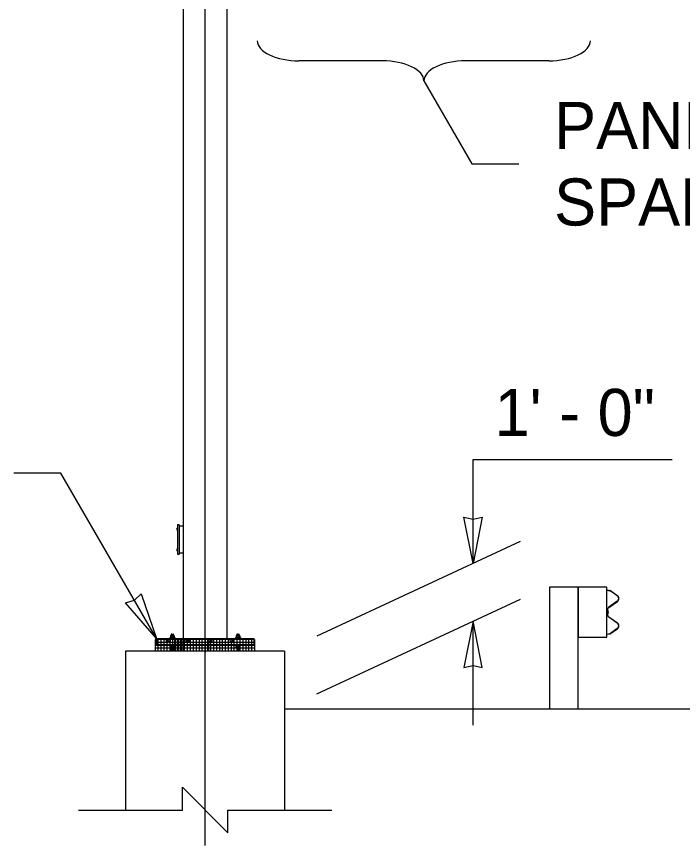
# Model space of a CAD drawing. Extents: x 99862 to 104211, y 98939 to 111076.
# Drawn here: x 100719.8 to 100945.9, y 100893.9 to 101175.5 of the extents above; entities that cross this region are included whole.
import ezdxf

# ---------------------------------------------------------------- set-up
doc = ezdxf.new("R2010")
doc.units = 0
for name, color, linetype in [('Level 15', 7, 'Continuous'), ('Level 20', 7, 'Continuous'), ('Level 22', 7, 'Continuous'), ('Level 3', 7, 'Continuous'), ('Level 36', 7, 'Continuous'), ('Level 4', 7, 'Continuous'), ('Level 6', 7, 'Continuous'), ('Level 62', 7, 'Continuous'), ('Level 7', 7, 'Continuous'), ('Level 9', 7, 'Continuous')]:
    doc.layers.add(name, color=color, linetype=linetype)

msp = doc.modelspace()

# ---------------------------------------------------------------- linework, layer by layer
at = {"layer": 'Level 15'}
for p, q in [((100783.8, 100893.86), (100783.8, 101626.74)), ((100843.96, 101160.49), (100815.67, 101160.49)), ((100900.53, 101160.49), (100872.25, 101160.49)), ((100858.1, 101153.67), (100874.35, 101125.52)), ((100874.35, 101125.52), (100890.35, 101125.52)), ((100874.8, 100989.71), (100874.8, 101025.02)), ((100874.8, 101025.02), (100942.43, 101025.02)), ((100734.8, 101020.38), (100718.8, 101020.38)), ((100767.3, 100964.24), (100734.8, 101020.38)), ((100890.8, 100997.17), (100821.75, 100964.97)), ((100890.8, 100977.48), (100821.64, 100945.23)), ((100874.8, 100934.71), (100874.8, 100970.02))]:
    msp.add_line(p, q, dxfattribs=at)
for points in [[(100874.8, 100989.71), (100871.72, 101005.43), (100874.8, 101004.71), (100877.89, 101005.43)], [(100767.3, 100964.24), (100756.77, 100976.32), (100759.81, 100977.23), (100762.11, 100979.4)], [(100874.8, 100970.02), (100871.72, 100954.3), (100874.8, 100955.02), (100877.89, 100954.3)]]:
    msp.add_lwpolyline(points, close=True, dxfattribs=at)
msp.add_lwpolyline([(100740.8, 100905.86), (100776.06, 100905.86), (100776.06, 100913.61), (100791.55, 100898.12), (100791.55, 100905.86), (100826.8, 100905.86)], dxfattribs=at)
for centre, major_axis, start_param, end_param in [((100815.67, 101167.3), (-14.14, 0), 6.283174, 7.853982), ((100900.53, 101167.3), (14.14, 0), 4.712389, 6.283196), ((100843.96, 101153.67), (14.14, 0), 6.283174, 7.853982), ((100872.25, 101153.67), (-14.14, 0), 4.712389, 6.283196)]:
    msp.add_ellipse(centre, major_axis=major_axis, ratio=0.481891, start_param=start_param, end_param=end_param, dxfattribs=at)
at = {"layer": 'Level 22'}
for p, q in [((100766.8, 100963.88), (100766.8, 100959.86)), ((100769.22, 100963.84), (100766.8, 100963.84)), ((100770.93, 100962.85), (100766.8, 100962.85)), ((100800.58, 100961.86), (100766.8, 100961.86)), ((100767.79, 100963.88), (100767.79, 100963.02)), ((100767.79, 100963.02), (100767.79, 100959.86)), ((100768.79, 100963.88), (100768.79, 100963.02)), ((100768.79, 100963.02), (100768.79, 100959.87)), ((100770.86, 100963.84), (100769.22, 100963.84)), ((100769.78, 100963.88), (100769.78, 100959.86)), ((100770.77, 100963.88), (100770.77, 100963.74)), ((100770.77, 100963.01), (100770.77, 100959.86)), ((100774.51, 100962.85), (100771.65, 100962.85)), ((100774.51, 100963.84), (100771.72, 100963.84)), ((100771.76, 100963.88), (100771.76, 100963.8)), ((100771.76, 100962.95), (100771.76, 100959.86)), ((100772.75, 100963.88), (100772.75, 100959.86)), ((100773.4, 100963.88), (100773.4, 100959.86)), ((100773.75, 100963.88), (100773.75, 100959.86)), ((100774.39, 100963.88), (100774.39, 100959.86)), ((100777.54, 100963.84), (100774.51, 100963.84)), ((100777.63, 100962.85), (100774.51, 100962.85)), ((100774.74, 100963.88), (100774.74, 100959.86)), ((100775.38, 100963.88), (100775.38, 100959.86)), ((100775.73, 100963.88), (100775.73, 100959.86)), ((100776.38, 100963.88), (100776.38, 100959.86)), ((100776.72, 100963.88), (100776.72, 100959.86)), ((100777.46, 100963.88), (100777.46, 100963.73)), ((100777.72, 100962.8), (100777.72, 100959.86)), ((100784.52, 100962.85), (100778.34, 100962.85)), ((100784.57, 100963.84), (100778.42, 100963.84)), ((100778.45, 100963.88), (100778.45, 100963.8)), ((100778.72, 100963.88), (100778.72, 100959.86)), ((100779.72, 100963.88), (100779.72, 100959.86)), ((100780.72, 100963.88), (100780.72, 100959.86)), ((100781.72, 100963.88), (100781.72, 100959.86)), ((100782.69, 100963.88), (100782.69, 100959.86)), ((100783.67, 100963.88), (100783.67, 100959.86)), ((100785.11, 100962.85), (100784.5, 100962.85)), ((100785.04, 100963.84), (100784.57, 100963.84)), ((100784.66, 100963.89), (100784.66, 100959.86)), ((100785.65, 100962.76), (100785.65, 100959.86)), ((100792.58, 100962.85), (100785.83, 100962.85)), ((100787.01, 100963.84), (100785.9, 100963.84)), ((100786.65, 100963.88), (100786.65, 100962.95)), ((100786.65, 100962.95), (100786.65, 100959.86)), ((100790.52, 100963.84), (100787.01, 100963.84)), ((100787.64, 100963.88), (100787.64, 100959.86)), ((100788.63, 100963.88), (100788.63, 100959.86)), ((100789.62, 100963.88), (100789.62, 100959.86)), ((100792.53, 100963.84), (100790.52, 100963.84)), ((100790.61, 100963.88), (100790.61, 100959.86)), ((100791.61, 100963.88), (100791.61, 100959.86)), ((100792.49, 100963.88), (100792.49, 100963.8)), ((100792.6, 100962.85), (100792.6, 100959.86)), ((100792.6, 100962.85), (100792.6, 100962.85)), ((100800.58, 100962.85), (100793.32, 100962.85)), ((100800.58, 100963.84), (100793.39, 100963.84)), ((100793.59, 100963.88), (100793.59, 100959.86)), ((100794.58, 100963.88), (100794.58, 100959.86)), ((100795.58, 100963.88), (100795.58, 100959.86)), ((100796.58, 100963.88), (100796.58, 100959.86)), ((100797.58, 100963.88), (100797.58, 100959.86)), ((100798.58, 100963.88), (100798.58, 100959.86)), ((100799.58, 100963.88), (100799.58, 100959.86)), ((100800.58, 100963.84), (100800.58, 100959.86)), ((100800.58, 100960.87), (100766.8, 100960.87))]:
    msp.add_line(p, q, dxfattribs=at)
for centre in [(100771.29, 100963.37), (100777.98, 100963.37), (100785.47, 100963.37), (100792.96, 100963.37)]:
    msp.add_circle(centre, 0.635, dxfattribs=at)
at = {"layer": 'Level 3'}
for p, q in [((100776.3, 101460.3), (100776.3, 101002.33)), ((100791.3, 101002.33), (100791.3, 101340.4))]:
    msp.add_line(p, q, dxfattribs=at)
at = {"layer": 'Level 36'}
msp.add_line((100920.47, 100973.94), (100920.47, 100972.34), dxfattribs=at)
msp.add_arc((100919.82, 100973.14), 1.03, 309.0733, 50.9267, dxfattribs=at)
at = {"layer": 'Level 4'}
for p, q in [((100776.3, 101002.33), (100776.3, 100964.24)), ((100791.3, 100964.24), (100791.3, 101002.33)), ((100920.32, 100980.68), (100920.3, 100980.6)), ((100920.3, 100980.6), (100921.29, 100980.43)), ((100920.32, 100980.68), (100921.3, 100980.5)), ((100923.79, 100978.72), (100921.47, 100980.35)), ((100921.51, 100980.42), (100923.84, 100978.78)), ((100923.79, 100976.85), (100920.91, 100974.82)), ((100920.95, 100974.76), (100923.84, 100976.79)), ((100920.39, 100973.14), (100920.39, 100973.82)), ((100920.39, 100973.14), (100920.39, 100972.45)), ((100920.47, 100973.14), (100920.47, 100973.82)), ((100920.47, 100973.14), (100920.47, 100972.45)), ((100923.79, 100969.43), (100920.91, 100971.46)), ((100920.95, 100971.52), (100923.84, 100969.49)), ((100923.79, 100967.56), (100921.47, 100965.92)), ((100921.51, 100965.86), (100923.84, 100967.49)), ((100920.3, 100965.67), (100921.29, 100965.84)), ((100920.32, 100965.6), (100920.3, 100965.67)), ((100920.32, 100965.6), (100921.3, 100965.77))]:
    msp.add_line(p, q, dxfattribs=at)
for centre, radius, start, end in [((100921.21, 100979.98), 0.457, 54.8459, 80), ((100921.21, 100979.98), 0.533, 54.852, 80), ((100923.14, 100977.78), 1.14, 305.1469, 54.8387), ((100923.14, 100977.78), 1.22, 305.1461, 54.8378), ((100921.61, 100973.82), 1.22, 125.1621, 180), ((100921.61, 100973.82), 1.14, 125.1612, 179.9897), ((100921.61, 100972.45), 1.22, 180, 234.8379), ((100921.61, 100972.45), 1.14, 180.0103, 234.8388), ((100923.14, 100968.49), 1.14, 305.1613, 54.8531), ((100923.14, 100968.49), 1.22, 305.1622, 54.8539), ((100921.21, 100966.29), 0.457, 280, 305.1541), ((100921.21, 100966.29), 0.533, 280, 305.148)]:
    msp.add_arc(centre, radius, start, end, dxfattribs=at)
at = {"layer": 'Level 6'}
for p, q in [((100776.55, 100964.08), (100776.55, 100963.65)), ((100776.55, 100963.05), (100776.55, 100962.62)), ((100776.55, 100962.03), (100776.55, 100961.59)), ((100776.55, 100960.8), (100776.55, 100960.36))]:
    msp.add_line(p, q, dxfattribs=at)
at = {"layer": 'Level 62'}
for points, degree in [([(100773.04, 100965.54), (100773.05, 100965.53), (100773.01, 100965.52), (100772.93, 100965.52), (100772.69, 100965.51), (100772.38, 100965.49), (100772.3, 100965.48), (100772.3, 100965.48), (100772.29, 100965.48), (100772.29, 100965.47)], 4), ([(100772.48, 100965.62), (100772.39, 100965.61), (100772.33, 100965.61), (100772.3, 100965.6)], 3), ([(100773.04, 100965.16), (100773.05, 100965.16), (100773.03, 100965.15), (100772.99, 100965.15)], 3), ([(100795.32, 100965.54), (100795.32, 100965.53), (100795.28, 100965.52), (100795.2, 100965.52), (100794.97, 100965.51), (100794.66, 100965.49), (100794.58, 100965.48), (100794.57, 100965.48), (100794.57, 100965.48), (100794.57, 100965.47)], 4), ([(100794.76, 100965.62), (100794.66, 100965.61), (100794.6, 100965.61), (100794.58, 100965.6)], 3), ([(100795.32, 100965.16), (100795.32, 100965.16), (100795.3, 100965.15), (100795.26, 100965.15)], 3), ([(100772.97, 100960.28), (100772.98, 100960.27), (100772.96, 100960.27), (100772.93, 100960.27), (100772.78, 100960.25), (100772.51, 100960.24), (100772.38, 100960.23), (100772.36, 100960.23), (100772.34, 100960.23), (100772.34, 100960.22)], 4), ([(100772.97, 100960.07), (100772.98, 100960.06), (100772.96, 100960.06), (100772.93, 100960.05), (100772.78, 100960.04), (100772.51, 100960.03), (100772.38, 100960.02), (100772.36, 100960.02), (100772.34, 100960.02), (100772.34, 100960.01)], 4), ([(100772.99, 100961.05), (100773, 100961.04), (100772.98, 100961.04), (100772.94, 100961.04), (100772.8, 100961.02), (100772.53, 100961.01), (100772.4, 100961), (100772.37, 100961), (100772.36, 100961), (100772.36, 100960.99)], 4), ([(100772.99, 100960.83), (100773, 100960.83), (100772.98, 100960.83), (100772.94, 100960.82), (100772.8, 100960.81), (100772.53, 100960.8), (100772.4, 100960.79), (100772.37, 100960.79), (100772.36, 100960.79), (100772.36, 100960.78)], 4), ([(100772.99, 100960.66), (100773, 100960.66), (100772.98, 100960.65), (100772.94, 100960.65), (100772.8, 100960.64), (100772.53, 100960.63), (100772.4, 100960.61), (100772.37, 100960.61), (100772.36, 100960.61), (100772.36, 100960.61)], 4), ([(100772.99, 100960.45), (100773, 100960.44), (100772.98, 100960.44), (100772.94, 100960.44), (100772.8, 100960.43), (100772.53, 100960.41), (100772.4, 100960.4), (100772.37, 100960.4), (100772.36, 100960.4), (100772.36, 100960.4)], 4), ([(100790.37, 100960.89), (100790.38, 100960.88), (100790.36, 100960.88), (100790.32, 100960.88), (100790.18, 100960.87), (100789.91, 100960.85), (100789.78, 100960.84), (100789.76, 100960.84), (100789.74, 100960.84), (100789.74, 100960.84)], 4), ([(100795.27, 100961.09), (100795.28, 100961.08), (100795.26, 100961.08), (100795.22, 100961.08), (100795.07, 100961.06), (100794.8, 100961.05), (100794.68, 100961.04), (100794.66, 100961.04), (100794.64, 100961.04), (100794.64, 100961.03)], 4), ([(100795.27, 100960.88), (100795.28, 100960.87), (100795.26, 100960.87), (100795.23, 100960.87), (100795.08, 100960.85), (100794.81, 100960.84), (100794.68, 100960.83), (100794.66, 100960.83), (100794.64, 100960.83), (100794.64, 100960.82)], 4), ([(100795.27, 100960.87), (100795.28, 100960.87), (100795.26, 100960.86), (100795.23, 100960.86), (100795.08, 100960.85), (100794.81, 100960.84), (100794.68, 100960.82), (100794.66, 100960.82), (100794.64, 100960.82), (100794.64, 100960.82)], 4), ([(100795.27, 100960.66), (100795.28, 100960.65), (100795.26, 100960.65), (100795.23, 100960.65), (100795.08, 100960.64), (100794.81, 100960.62), (100794.68, 100960.61), (100794.66, 100960.61), (100794.64, 100960.61), (100794.64, 100960.61)], 4), ([(100795.27, 100960.45), (100795.28, 100960.44), (100795.26, 100960.44), (100795.23, 100960.44), (100795.08, 100960.43), (100794.81, 100960.41), (100794.68, 100960.4), (100794.66, 100960.4), (100794.64, 100960.4), (100794.64, 100960.4)], 4), ([(100795.27, 100960.23), (100795.28, 100960.23), (100795.26, 100960.22), (100795.23, 100960.22), (100795.08, 100960.21), (100794.81, 100960.2), (100794.68, 100960.19), (100794.66, 100960.18), (100794.64, 100960.18), (100794.64, 100960.18)], 4), ([(100795.27, 100960.02), (100795.28, 100960.02), (100795.26, 100960.01), (100795.23, 100960.01), (100795.08, 100960), (100794.81, 100959.99), (100794.68, 100959.98), (100794.66, 100959.97), (100794.64, 100959.97), (100794.64, 100959.97)], 4)]:
    msp.add_open_spline(points, degree=degree, dxfattribs=at)
at = {"layer": 'Level 7'}
for p, q in [((100910.55, 100981.67), (100900.8, 100981.67)), ((100900.8, 100981.67), (100900.8, 100940.18)), ((100910.55, 100940.18), (100910.55, 100981.67)), ((100767.3, 100964.24), (100767.3, 100961.99)), ((100767.3, 100964.24), (100800.3, 100964.24)), ((100800.3, 100964.24), (100800.3, 100961.99)), ((100800.3, 100961.99), (100767.3, 100961.99)), ((100810.8, 100959.86), (100756.8, 100959.86)), ((100756.8, 100959.86), (100756.8, 100905.86)), ((100810.8, 100959.86), (100810.8, 100905.86)), ((102186.87, 100940.18), (100810.8, 100940.18))]:
    msp.add_line(p, q, dxfattribs=at)
msp.add_lwpolyline([(100920.3, 100981.67), (100910.55, 100981.67), (100910.55, 100964.61), (100920.3, 100964.61)], close=True, dxfattribs=at)
at = {"layer": 'Level 9'}
for p, q in [((100774.43, 101002.8), (100774.43, 100999.33)), ((100774.99, 101002.8), (100774.43, 101002.8)), ((100774.99, 101002.8), (100774.99, 100999.33)), ((100776.3, 101002.33), (100774.99, 101002.33)), ((100774.43, 100999.33), (100774.43, 100996.33)), ((100774.99, 100999.33), (100774.99, 100996.33)), ((100774.43, 100996.33), (100774.43, 100992.86)), ((100774.99, 100996.33), (100774.99, 100992.86)), ((100774.43, 100992.86), (100774.99, 100992.86)), ((100774.99, 100993.33), (100776.3, 100993.33)), ((100771.83, 100964.49), (100773.5, 100964.49)), ((100771.83, 100964.49), (100771.83, 100964.37)), ((100771.83, 100964.37), (100773.5, 100964.37)), ((100771.83, 100964.37), (100771.83, 100964.24)), ((100771.83, 100964.24), (100773.5, 100964.24)), ((100772.1, 100965.15), (100772.02, 100965.1)), ((100772.02, 100965.1), (100772.02, 100964.49)), ((100772.34, 100964.49), (100772.02, 100964.49)), ((100772.18, 100965.15), (100772.1, 100965.15)), ((100772.18, 100965.15), (100772.18, 100965.15)), ((100772.65, 100965.15), (100772.18, 100965.15)), ((100772.38, 100965.67), (100772.29, 100965.62)), ((100772.29, 100965.62), (100772.29, 100965.15)), ((100772.34, 100965.1), (100772.34, 100964.49)), ((100772.99, 100964.49), (100772.34, 100964.49)), ((100772.38, 100965.67), (100772.95, 100965.67)), ((100772.68, 100965.15), (100772.65, 100965.15)), ((100773.15, 100965.15), (100772.68, 100965.15)), ((100773.04, 100965.62), (100772.95, 100965.67)), ((100772.95, 100965.67), (100772.95, 100965.67)), ((100772.99, 100965.1), (100772.99, 100964.49)), ((100773.32, 100964.49), (100772.99, 100964.49)), ((100773.04, 100965.15), (100773.04, 100965.62)), ((100773.16, 100965.15), (100773.15, 100965.15)), ((100773.23, 100965.15), (100773.16, 100965.15)), ((100773.32, 100965.1), (100773.23, 100965.15)), ((100773.32, 100965.1), (100773.32, 100964.49)), ((100773.5, 100964.49), (100773.5, 100964.37)), ((100773.5, 100964.37), (100773.5, 100964.24)), ((100794.11, 100964.49), (100795.77, 100964.49)), ((100794.11, 100964.49), (100794.11, 100964.37)), ((100794.11, 100964.37), (100795.77, 100964.37)), ((100794.11, 100964.37), (100794.11, 100964.24)), ((100794.11, 100964.24), (100795.77, 100964.24)), ((100794.38, 100965.15), (100794.29, 100965.1)), ((100794.29, 100965.1), (100794.29, 100964.49)), ((100794.62, 100964.49), (100794.29, 100964.49)), ((100794.45, 100965.15), (100794.38, 100965.15)), ((100794.46, 100965.15), (100794.45, 100965.15)), ((100794.93, 100965.15), (100794.46, 100965.15)), ((100794.66, 100965.67), (100794.57, 100965.62)), ((100794.57, 100965.62), (100794.57, 100965.15)), ((100794.62, 100965.1), (100794.62, 100964.49)), ((100795.26, 100964.49), (100794.62, 100964.49)), ((100794.66, 100965.67), (100795.23, 100965.67)), ((100794.95, 100965.15), (100794.93, 100965.15)), ((100795.42, 100965.15), (100794.95, 100965.15)), ((100795.32, 100965.62), (100795.23, 100965.67)), ((100795.23, 100965.67), (100795.23, 100965.67)), ((100795.26, 100965.1), (100795.26, 100964.49)), ((100795.59, 100964.49), (100795.26, 100964.49)), ((100795.32, 100965.15), (100795.32, 100965.62)), ((100795.43, 100965.15), (100795.42, 100965.15)), ((100795.5, 100965.15), (100795.43, 100965.15)), ((100795.59, 100965.1), (100795.5, 100965.15)), ((100795.59, 100965.1), (100795.59, 100964.49)), ((100795.77, 100964.49), (100795.77, 100964.37)), ((100795.77, 100964.37), (100795.77, 100964.24)), ((100771.12, 100963.67), (100770.94, 100963.37)), ((100770.94, 100963.37), (100771.12, 100963.07)), ((100771.46, 100963.67), (100771.12, 100963.67)), ((100771.12, 100963.07), (100771.46, 100963.07)), ((100771.64, 100963.37), (100771.46, 100963.67)), ((100771.46, 100963.07), (100771.64, 100963.37)), ((100771.83, 100961.99), (100771.83, 100961.87)), ((100771.83, 100961.87), (100773.5, 100961.87)), ((100772.02, 100961.26), (100772.02, 100961.87)), ((100772.34, 100961.87), (100772.02, 100961.87)), ((100772.29, 100961.42), (100772.29, 100959.86)), ((100772.34, 100961.26), (100772.34, 100961.87)), ((100772.99, 100961.87), (100772.34, 100961.87)), ((100773.32, 100961.87), (100772.99, 100961.87)), ((100772.99, 100961.26), (100772.99, 100961.87)), ((100773.04, 100959.86), (100773.04, 100961.42)), ((100773.32, 100961.26), (100773.32, 100961.87)), ((100773.5, 100961.99), (100773.5, 100961.87)), ((100777.81, 100963.67), (100777.64, 100963.37)), ((100777.64, 100963.37), (100777.81, 100963.07)), ((100778.15, 100963.67), (100777.81, 100963.67)), ((100777.81, 100963.07), (100778.15, 100963.07)), ((100778.33, 100963.37), (100778.15, 100963.67)), ((100778.15, 100963.07), (100778.33, 100963.37)), ((100782.64, 100963.89), (100782.64, 100959.86)), ((100783.81, 100963.89), (100783.81, 100959.53)), ((100784.99, 100963.69), (100784.99, 100963.59)), ((100784.99, 100962.95), (100784.99, 100959.86)), ((100785.3, 100963.67), (100785.12, 100963.37)), ((100785.12, 100963.37), (100785.3, 100963.07)), ((100785.64, 100963.67), (100785.3, 100963.67)), ((100785.3, 100963.07), (100785.64, 100963.07)), ((100785.82, 100963.37), (100785.64, 100963.67)), ((100785.64, 100963.07), (100785.82, 100963.37)), ((100792.79, 100963.67), (100792.61, 100963.37)), ((100792.61, 100963.37), (100792.79, 100963.07)), ((100793.13, 100963.67), (100792.79, 100963.67)), ((100792.79, 100963.07), (100793.13, 100963.07)), ((100793.31, 100963.37), (100793.13, 100963.67)), ((100793.13, 100963.07), (100793.31, 100963.37)), ((100794.11, 100961.99), (100795.77, 100961.99)), ((100794.11, 100961.99), (100794.11, 100961.87)), ((100794.11, 100961.87), (100795.77, 100961.87)), ((100794.29, 100961.26), (100794.29, 100961.87)), ((100794.62, 100961.87), (100794.29, 100961.87)), ((100794.57, 100961.42), (100794.57, 100959.86)), ((100794.62, 100961.26), (100794.62, 100961.87)), ((100795.26, 100961.87), (100794.62, 100961.87)), ((100795.59, 100961.87), (100795.26, 100961.87)), ((100795.26, 100961.26), (100795.26, 100961.87)), ((100795.32, 100959.86), (100795.32, 100961.42)), ((100795.59, 100961.26), (100795.59, 100961.87)), ((100795.77, 100961.99), (100795.77, 100961.87)), ((100772.1, 100961.21), (100772.02, 100961.26)), ((100772.65, 100961.21), (100772.1, 100961.21)), ((100772.68, 100961.21), (100772.65, 100961.21)), ((100773.15, 100961.21), (100772.68, 100961.21)), ((100773.16, 100961.21), (100773.15, 100961.21)), ((100773.23, 100961.21), (100773.16, 100961.21)), ((100773.23, 100961.21), (100773.32, 100961.26)), ((100794.29, 100961.26), (100794.38, 100961.21)), ((100794.45, 100961.21), (100794.38, 100961.21)), ((100794.46, 100961.21), (100794.45, 100961.21)), ((100794.93, 100961.21), (100794.46, 100961.21)), ((100794.95, 100961.21), (100794.93, 100961.21)), ((100795.42, 100961.21), (100794.95, 100961.21)), ((100795.43, 100961.21), (100795.42, 100961.21)), ((100795.5, 100961.21), (100795.43, 100961.21)), ((100795.5, 100961.21), (100795.59, 100961.26))]:
    msp.add_line(p, q, dxfattribs=at)
for centre in [(100774.43, 101001.3), (100774.43, 100994.36)]:
    msp.add_arc(centre, 0.305, 90, 270, dxfattribs=at)
for points, degree in [([(100772.18, 100965.15), (100772.15, 100965.15), (100772.12, 100965.14), (100772.07, 100965.13), (100772.04, 100965.11), (100772.02, 100965.1)], 3), ([(100772.34, 100965.1), (100772.29, 100965.13), (100772.24, 100965.15), (100772.18, 100965.15)], 2), ([(100772.29, 100965.62), (100772.29, 100965.62), (100772.29, 100965.62), (100772.3, 100965.62), (100772.3, 100965.62), (100772.32, 100965.62), (100772.35, 100965.62), (100772.38, 100965.62)], 3), ([(100772.65, 100965.15), (100772.6, 100965.15), (100772.55, 100965.14), (100772.44, 100965.13), (100772.39, 100965.11), (100772.34, 100965.1)], 3), ([(100772.38, 100965.62), (100772.4, 100965.62), (100772.42, 100965.62), (100772.45, 100965.62), (100772.47, 100965.62), (100772.52, 100965.62), (100772.54, 100965.62), (100772.59, 100965.62), (100772.61, 100965.62), (100772.66, 100965.62), (100772.69, 100965.62), (100772.74, 100965.62), (100772.76, 100965.62), (100772.83, 100965.62), (100772.87, 100965.62), (100772.93, 100965.62), (100772.95, 100965.62), (100772.98, 100965.62), (100772.99, 100965.62), (100773.01, 100965.62), (100773.02, 100965.62), (100773.03, 100965.62), (100773.04, 100965.62), (100773.04, 100965.62), (100773.04, 100965.62), (100773.04, 100965.62)], 3), ([(100772.99, 100965.1), (100772.94, 100965.11), (100772.89, 100965.13), (100772.78, 100965.14), (100772.73, 100965.15), (100772.68, 100965.15)], 3), ([(100773.15, 100965.15), (100773.09, 100965.15), (100773.04, 100965.13), (100772.99, 100965.1)], 2), ([(100773.32, 100965.1), (100773.26, 100965.13), (100773.21, 100965.15), (100773.16, 100965.15)], 2), ([(100773.31, 100965.1), (100773.31, 100965.1), (100773.32, 100965.1), (100773.32, 100965.1)], 2), ([(100794.45, 100965.15), (100794.42, 100965.15), (100794.4, 100965.14), (100794.34, 100965.13), (100794.32, 100965.11), (100794.29, 100965.1)], 3), ([(100794.62, 100965.1), (100794.56, 100965.13), (100794.51, 100965.15), (100794.46, 100965.15)], 2), ([(100794.57, 100965.62), (100794.57, 100965.62), (100794.57, 100965.62), (100794.57, 100965.62), (100794.58, 100965.62), (100794.6, 100965.62), (100794.62, 100965.62), (100794.66, 100965.62)], 3), ([(100794.93, 100965.15), (100794.87, 100965.15), (100794.82, 100965.14), (100794.72, 100965.13), (100794.67, 100965.11), (100794.62, 100965.1)], 3), ([(100794.66, 100965.62), (100794.67, 100965.62), (100794.69, 100965.62), (100794.73, 100965.62), (100794.75, 100965.62), (100794.79, 100965.62), (100794.82, 100965.62), (100794.86, 100965.62), (100794.89, 100965.62), (100794.94, 100965.62), (100794.96, 100965.62), (100795.01, 100965.62), (100795.03, 100965.62), (100795.1, 100965.62), (100795.15, 100965.62), (100795.2, 100965.62), (100795.22, 100965.62), (100795.25, 100965.62), (100795.26, 100965.62), (100795.29, 100965.62), (100795.29, 100965.62), (100795.31, 100965.62), (100795.31, 100965.62), (100795.31, 100965.62), (100795.32, 100965.62), (100795.32, 100965.62)], 3), ([(100795.26, 100965.1), (100795.21, 100965.11), (100795.16, 100965.13), (100795.06, 100965.14), (100795.01, 100965.15), (100794.95, 100965.15)], 3), ([(100795.42, 100965.15), (100795.37, 100965.15), (100795.32, 100965.13), (100795.26, 100965.1)], 2), ([(100795.59, 100965.1), (100795.54, 100965.13), (100795.49, 100965.15), (100795.43, 100965.15)], 2), ([(100795.59, 100965.1), (100795.59, 100965.1), (100795.59, 100965.1), (100795.59, 100965.1)], 2), ([(100772.34, 100961.26), (100772.29, 100961.23), (100772.24, 100961.21), (100772.18, 100961.21)], 2), ([(100772.65, 100961.21), (100772.6, 100961.21), (100772.55, 100961.22), (100772.44, 100961.24), (100772.39, 100961.25), (100772.34, 100961.26)], 3), ([(100772.99, 100961.26), (100772.94, 100961.25), (100772.89, 100961.23), (100772.78, 100961.22), (100772.73, 100961.21), (100772.68, 100961.21)], 3), ([(100773.15, 100961.21), (100773.09, 100961.21), (100773.04, 100961.23), (100772.99, 100961.26)], 2), ([(100773.32, 100961.26), (100773.26, 100961.23), (100773.21, 100961.21), (100773.16, 100961.21)], 2), ([(100773.31, 100961.26), (100773.31, 100961.26), (100773.32, 100961.26), (100773.32, 100961.26)], 2), ([(100794.45, 100961.21), (100794.42, 100961.21), (100794.4, 100961.22), (100794.34, 100961.23), (100794.32, 100961.25), (100794.29, 100961.26)], 3), ([(100794.62, 100961.26), (100794.56, 100961.23), (100794.51, 100961.21), (100794.46, 100961.21)], 2), ([(100794.6, 100960.62), (100794.6, 100960.62), (100794.6, 100960.62), (100794.6, 100960.62)], 2), ([(100794.93, 100961.21), (100794.87, 100961.21), (100794.82, 100961.22), (100794.72, 100961.24), (100794.67, 100961.25), (100794.62, 100961.26)], 3), ([(100795.26, 100961.26), (100795.21, 100961.25), (100795.16, 100961.23), (100795.06, 100961.22), (100795.01, 100961.21), (100794.95, 100961.21)], 3), ([(100795.42, 100961.21), (100795.37, 100961.21), (100795.32, 100961.23), (100795.26, 100961.26)], 2), ([(100795.59, 100961.26), (100795.54, 100961.23), (100795.49, 100961.21), (100795.43, 100961.21)], 2), ([(100795.59, 100961.26), (100795.59, 100961.26), (100795.59, 100961.26), (100795.59, 100961.26)], 2)]:
    msp.add_open_spline(points, degree=degree, dxfattribs=at)

# ---------------------------------------------------------------- texts
at = {"layer": 'Level 20'}
for s, p in [('PANEL LENGTH ', (100902.35, 101130.53)), ('SPAN AND NOT TO EXCEED ', (100902.35, 101104.53))]:
    msp.add_text(s, height=16, dxfattribs=at).set_placement(p)
msp.add_text('1\' - 0"', height=16, rotation=360, dxfattribs=at).set_placement((100882.13, 101033.02))

doc.saveas('drawing.dxf')
